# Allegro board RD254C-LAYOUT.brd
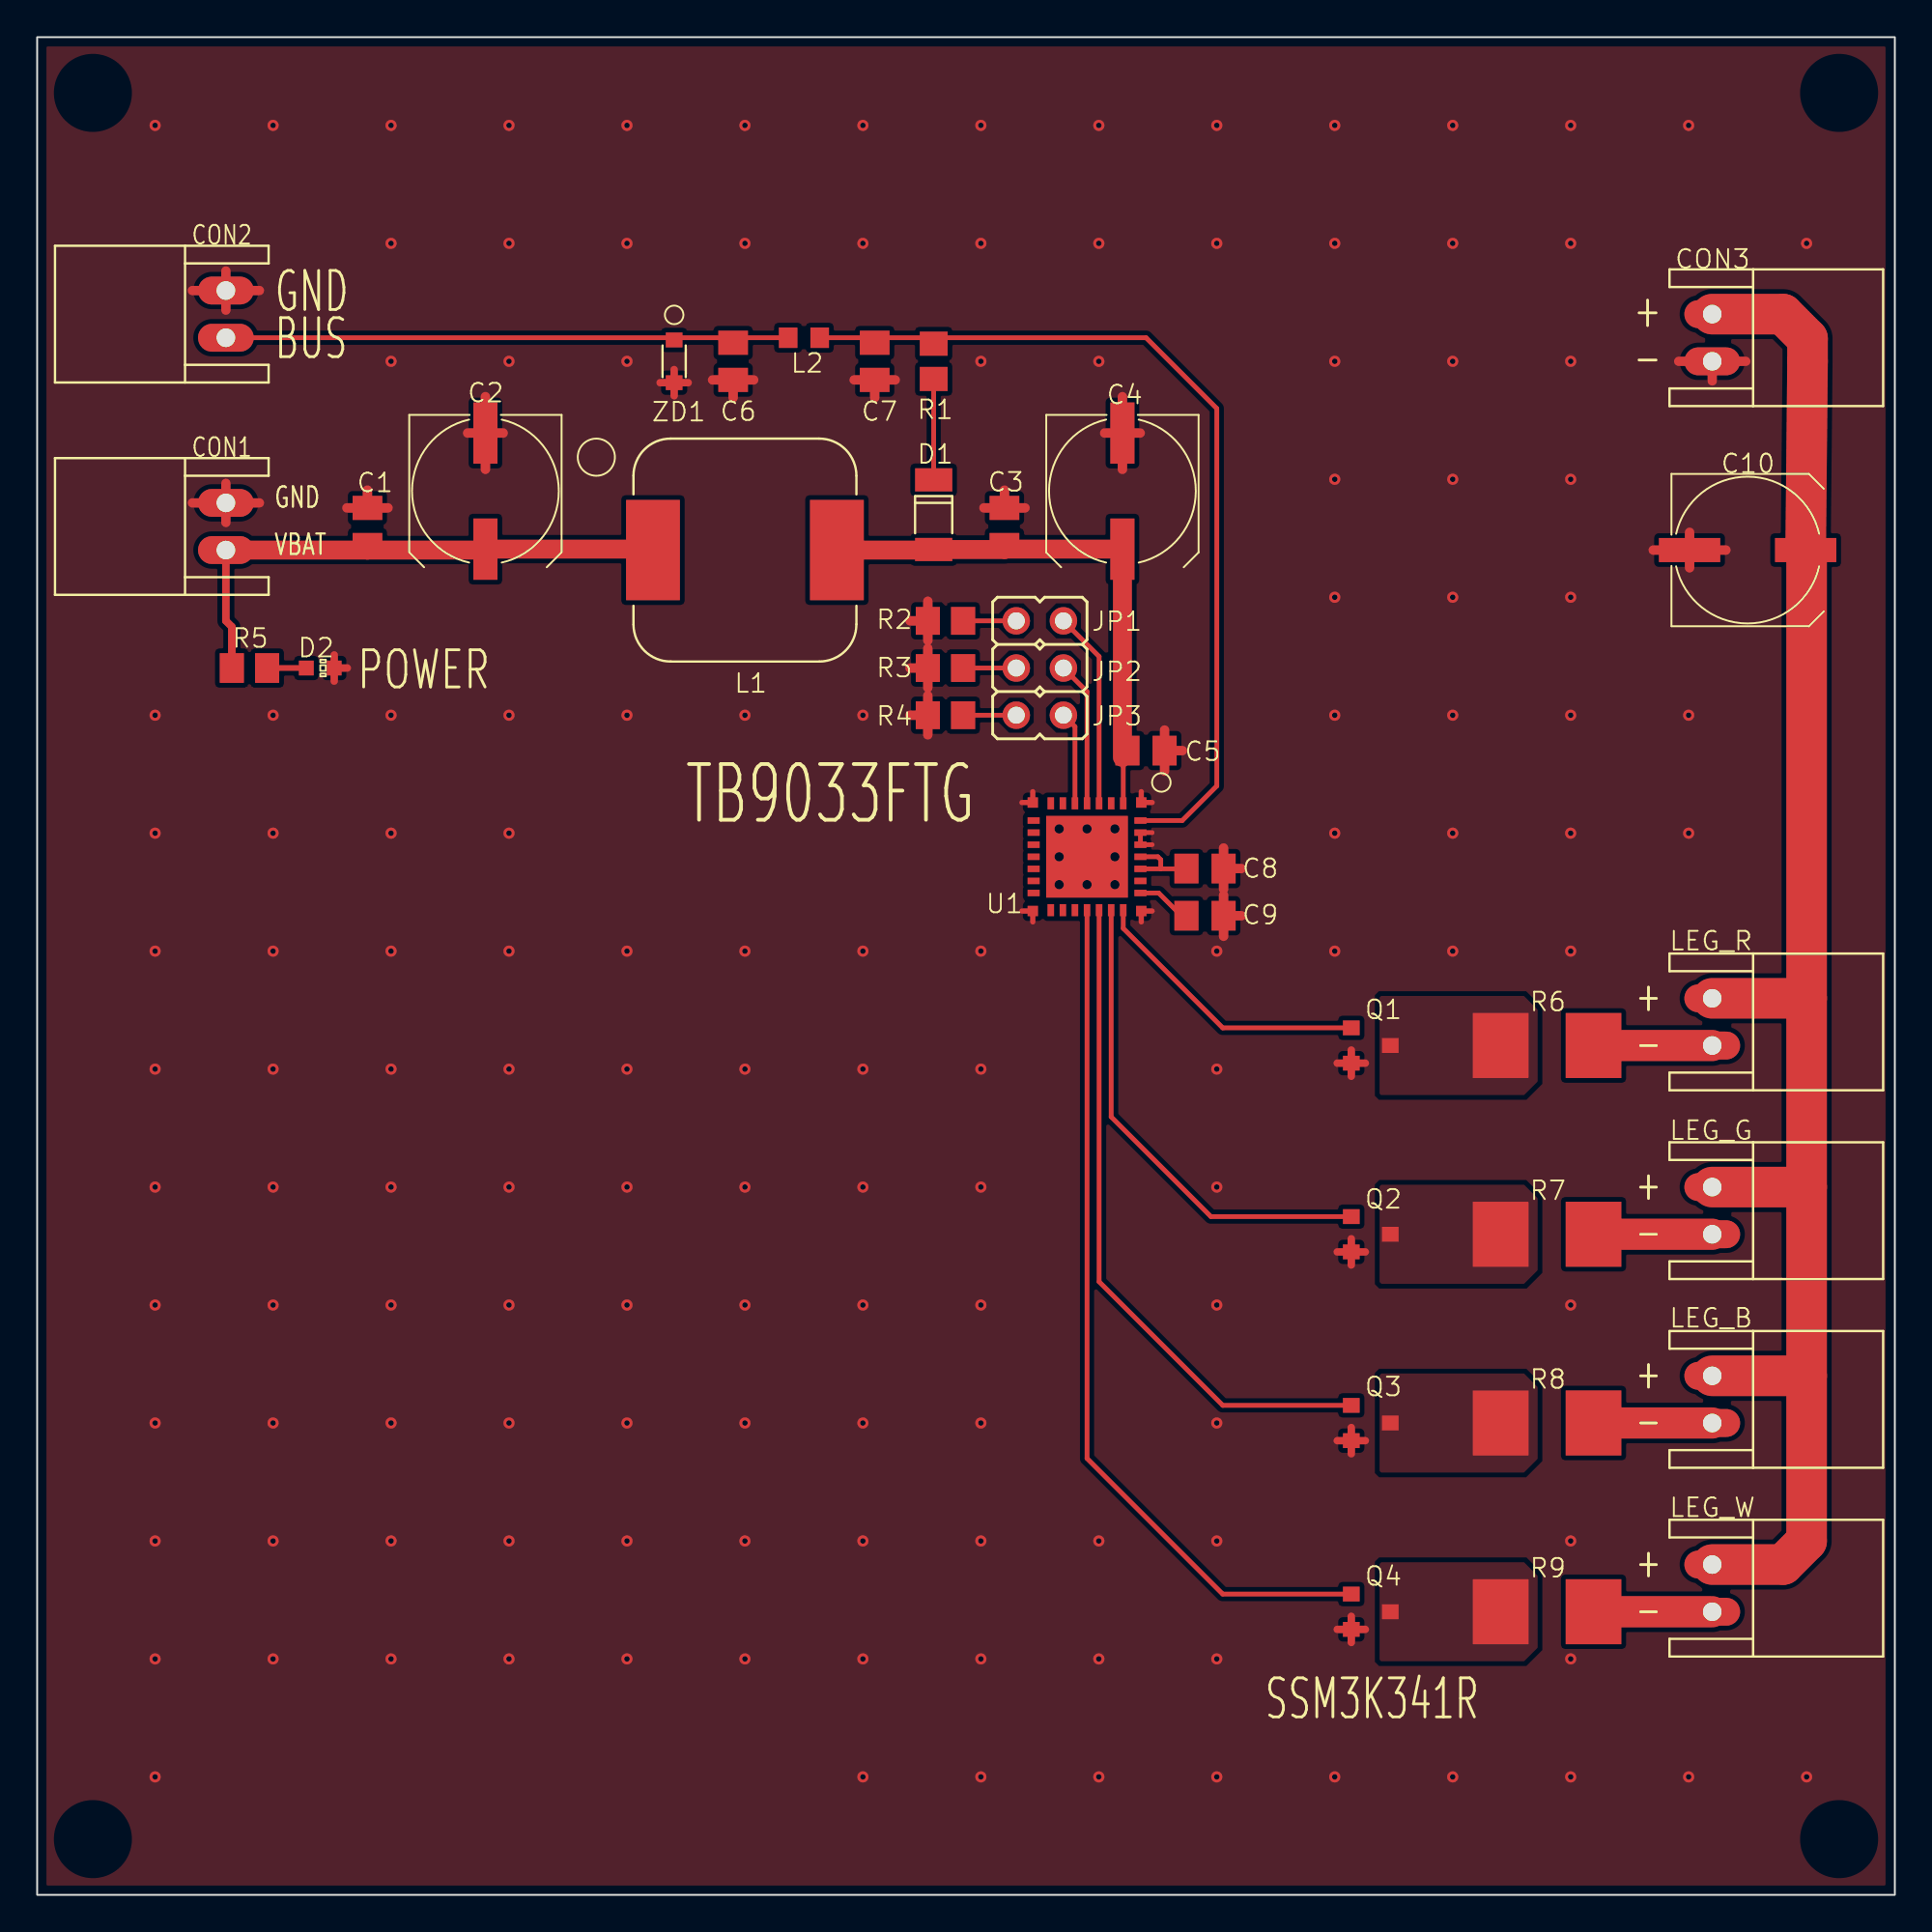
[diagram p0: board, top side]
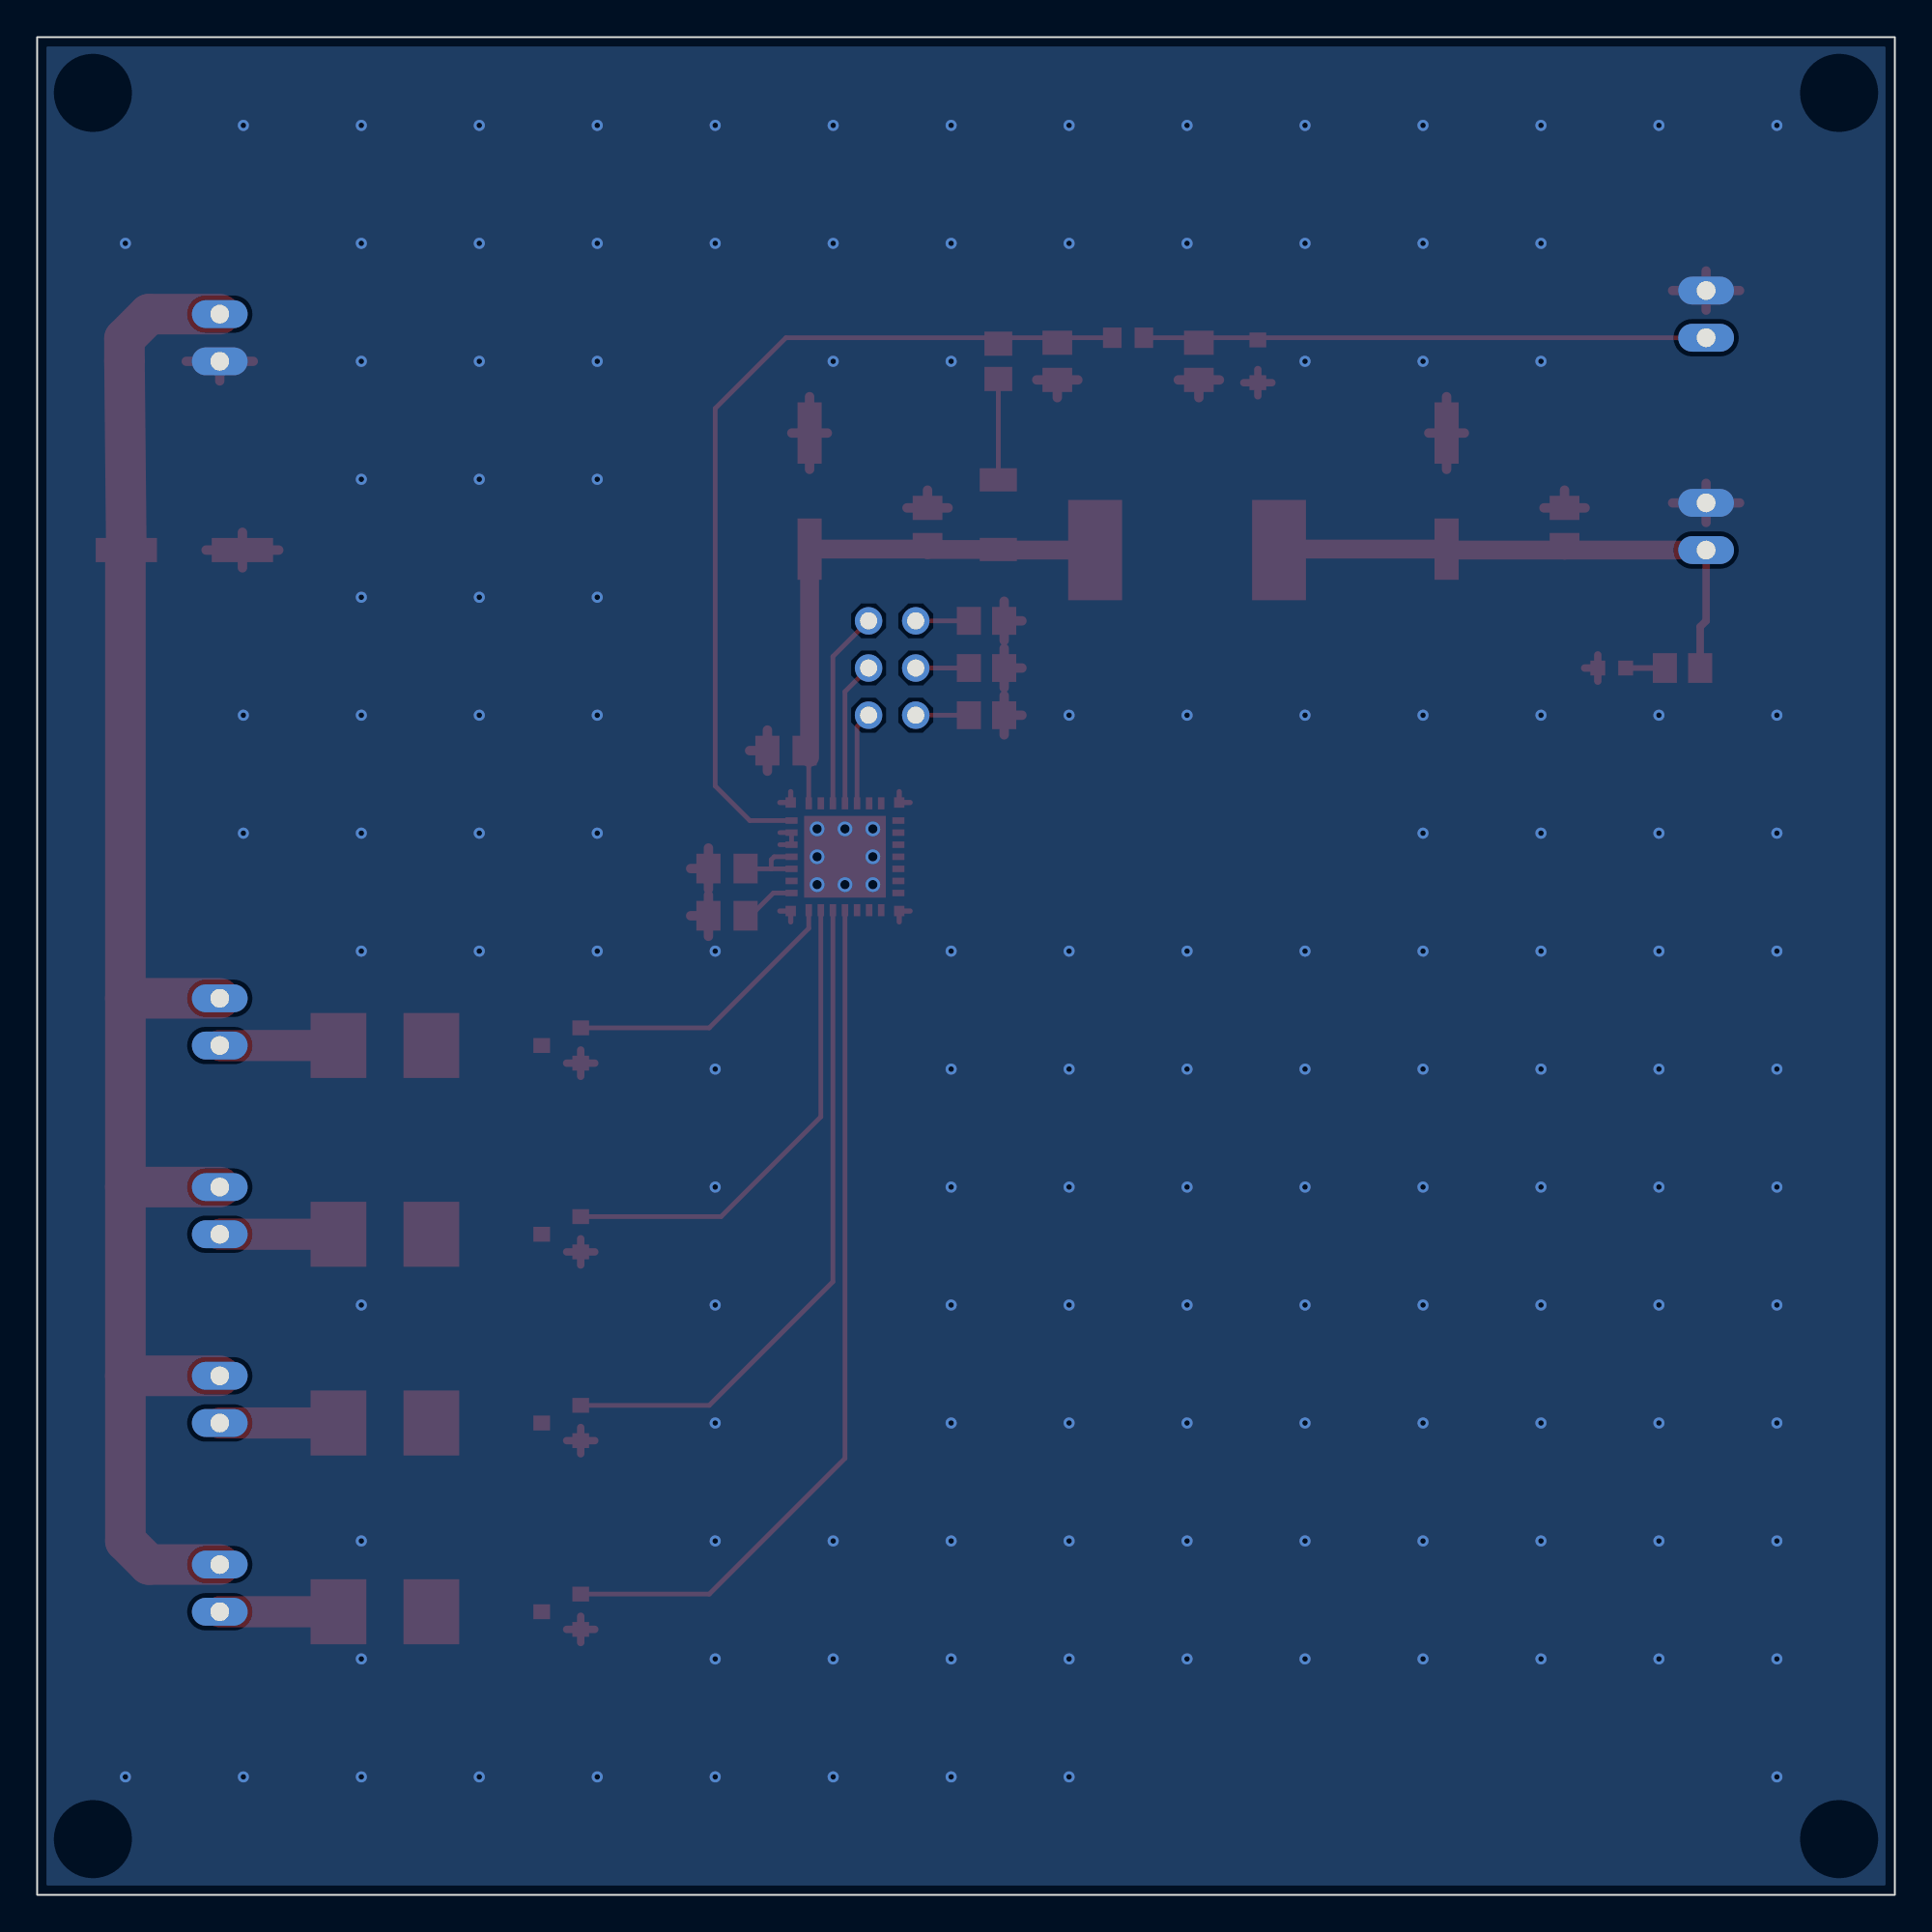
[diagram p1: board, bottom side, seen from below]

Outline 100 x 100 mm; copper layers: TOP, BOTTOM. Coordinates in mm from the lower left corner of the outline.
Outline path: rectangle 0,0 100,100

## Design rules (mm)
constraint set DEFAULT: 

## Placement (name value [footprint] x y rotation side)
C1  -  [C0805K]  17.78 73.66 90 top
C2  -  [UD_8X10_NICHICON_01]  24.13 75.56 270 top
C3  -  [C0805K]  52.07 73.66 90 top
C4  -  [UD_8X10_NICHICON_01]  58.42 75.56 270 top
C5  -  [C0805K]  59.69 61.59 0 top
C6  -  [C0805K]  37.47 82.55 270 top
C7  -  [C0805K]  45.09 82.55 270 top
C8  -  [C0805K]  62.87 55.24 180 top
C9  -  [C0805K]  62.87 52.7 180 top
C10  -  [UD_8X10_NICHICON_01]  92.08 72.39 0 top
CON1  -  [S2B_XH_A]  10.16 73.66 90 top
CON2  -  [S2B_XH_A]  10.16 85.09 90 top
CON3  -  [S2B_XH_A]  90.17 83.82 270 top
CON4  -  [S2B_XH_A]  90.17 46.99 270 top
CON5  -  [S2B_XH_A]  90.17 36.83 270 top
CON6  -  [S2B_XH_A]  90.17 26.67 270 top
CON7  -  [S2B_XH_A]  90.17 16.51 270 top
D1  -  [LL4148]  48.26 74.3 90 top
D2  -  [CHIP_LED0603]  15.24 66.04 270 top
JP1  -  [JP1]  53.98 68.58 270 top
JP2  -  [JP1]  53.98 66.04 270 top
JP3  -  [JP1]  53.98 63.5 270 top
L1  -  [7447709222]  38.1 72.39 270 top
L2  -  [R0603]  41.27 83.82 0 top
NOREF  -  []  -71 -47 0 top
Q1  -  [SOT_23F]  72.39 45.72 270 top
Q2  -  [SOT_23F]  72.39 35.56 270 top
Q3  -  [SOT_23F]  72.39 25.4 270 top
Q4  -  [SOT_23F]  72.39 15.24 270 top
R1  -  [R0805]  48.26 82.55 270 top
R2  -  [R0805]  48.9 68.58 180 top
R3  -  [R0805]  48.9 66.04 180 top
R4  -  [R0805]  48.9 63.5 180 top
R5  -  [M0805]  11.43 66.04 180 top
R6  -  [R2512_2010]  81.28 45.72 0 top
R7  -  [R2512_2010]  81.28 35.56 0 top
R8  -  [R2512_2010]  81.28 25.4 0 top
R9  -  [R2512_2010]  81.28 15.24 0 top
U1  -  [P_VQFN28_0606_0_65_003_01]  56.52 55.88 180 top
ZD1  -  [USC]  34.29 82.55 270 top

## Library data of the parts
C1 C3 C5-C9 = C0805K: alternate symbols: (T:C0805K,C1_C0805K,C3_C0805K,C5_C0805K,C6_C0805K,C7_C0805K,C8_C0805K,C9_C0805K;B:C0805K_bk)
C2 C4 C10 = UD-8X10_NICHICON_01: alternate symbols: (T:UD_8X10_NICHICON_01,C2_UD_8X10_NICHICON_01,C4_UD_8X10_NICHICON_01,C10_UD_8X10_NICHICON_01;B:UD_8X10_NICHICON_01_bk)
CON1-CON7 = S2B-XH-A: alternate symbols: (T:S2B_XH_A;B:S2B_XH_A_bk)
D1 = LL4148: alternate symbols: (T:LL4148;B:LL4148_bk)
D2 = CHIP-LED0603: alternate symbols: (T:CHIP_LED0603,D2_CHIP_LED0603;B:CHIP_LED0603_bk)
JP1-JP3 = JP1: alternate symbols: (T:JP1,JP1_JP1,JP2_JP1,JP3_JP1;B:JP1_bk)
L1 = 7447709222: alternate symbols: (T:7447709222;B:7447709222_bk)
L2 = R0603: alternate symbols: (T:R0603,L2_R0603;B:R0603_bk)
Q1-Q4 = SOT-23F: alternate symbols: (T:SOT_23F;B:SOT_23F_bk)
R1-R4 = R0805: alternate symbols: (T:R0805,R1_R0805,R2_R0805,R3_R0805,R4_R0805;B:R0805_bk)
R5 = M0805: alternate symbols: (T:M0805,R5_M0805;B:M0805_bk)
R6-R9 = R2512-2010: alternate symbols: (T:R2512_2010,R6_R2512_2010,R7_R2512_2010,R8_R2512_2010,R9_R2512_2010;B:R2512_2010_bk)
U1 = P-VQFN28-0606-0_65-003_01: alternate symbols: (T:P_VQFN28_0606_0_65_003_01,U1_P_VQFN28_0606_0_65_003_01;B:P_VQFN28_0606_0_65_003_01_bk)
ZD1 = USC: alternate symbols: (T:USC,ZD1_USC;B:USC_bk)

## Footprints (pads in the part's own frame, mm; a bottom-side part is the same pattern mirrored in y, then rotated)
7447709222
  rect 5.4x2.9 smd: 1(0,-4.95) 2(0,4.95)
C0805K
  rect 1.3x1.6 smd: 1(-1,0) 2(1,0)
CHIP_LED0603
  rect 0.8x0.8 smd: A(0,-0.75) C(0,0.75)
JP1
  round 1.48 hole 0.914: 1(0,-1.27) 2(0,1.27)
LL4148
  rect 1.25x2 smd: A(-1.875,0) K(1.875,0)
M0805
  rect 1.3x1.6 smd: 1(-0.95,0) 2(0.95,0)
P_VQFN28_0606_0_65_003_01
  rect 0.35x0.65 smd: 1(-1.95,-2.875) 2(-1.3,-2.875) 3(-0.65,-2.875) 4(0,-2.875) 5(0.65,-2.875) 6(1.3,-2.875) 7(1.95,-2.875) 15(1.95,2.875) 16(1.3,2.875) 17(0.65,2.875) 18(0,2.875) 19(-0.65,2.875) 20(-1.3,2.875) 21(-1.95,2.875)
  rect 0.56x0.56 smd: 1T(-2.92,-2.92) 2T(2.92,-2.92) 3T(2.92,2.92) 4T(-2.92,2.92)
  rect 0.65x0.35 smd: 8(2.875,-1.95) 9(2.875,-1.3) 10(2.875,-0.65) 11(2.875,0) 12(2.875,0.65) 13(2.875,1.3) 14(2.875,1.95) 22(-2.875,1.95) 23(-2.875,1.3) 24(-2.875,0.65) 25(-2.875,0) 26(-2.875,-0.65) 27(-2.875,-1.3) 28(-2.875,-1.95)
  rect 4.4x4.4 smd: E_PAD(0,0)
R0603
  rect 1x1.1 smd: 1(-0.85,0) 2(0.85,0)
R0805
  rect 1.3x1.5 smd: 1(-0.95,0) 2(0.95,0)
R2512_2010
  rect 3x3.5 smd: P_1(-2.5,0) P_2(2.5,0)
S2B_XH_A
  oval 1.5x3 hole 1: 1(1.27,0) 2(-1.27,0)
SOT_23F
  rect 0.8x0.9 smd: 1(-0.95,-1.65) 2(0.95,-1.65) 3(0,0.45)
UD_8X10_NICHICON_01
  rect 3.3x1.3 smd: 1(-3.125,0) 2(3.125,0)
USC
  rect 0.8x0.9 smd: 1(-1.15,0) 2(1.15,0)

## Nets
+12V: C1.1 C2.2 CON1.2 L1.1 R5.2
GND: C1.2 C2.1 C3.2 C4.1 C5.2 C6.2 C7.2 C8.1 C9.1 C10.1 CON1.1 CON2.1 CON3.1 D2.C Q1.2 Q2.2 Q3.2 Q4.2 R2.2 R3.2 R4.2 U1.1T U1.2T U1.3T U1.4T U1.26 U1.27 U1.E_PAD ZD1.2
VCC: C8.2 U1.24 U1.25
VDD: C9.2 U1.22
BUS: C3.1 C4.2 C5.1 C6.1 C7.1 CON2.2 D1.A D1.K L1.2 L2.1 L2.2 R1.1 R1.2 U1.1 U1.28 ZD1.1
N_2: JP1.1 JP1.2 R2.1 U1.3
N_3: JP2.1 JP2.2 R3.1 U1.4
N_4: JP3.1 JP3.2 R4.1 U1.5
N_5: C10.2 CON3.2 CON4.1 CON4.2 CON5.1 CON5.2 CON6.1 CON6.2 CON7.1 CON7.2 R6.P_2 R7.P_2 R8.P_2 R9.P_2
N_10: Q1.3 R6.P_1
N_11: Q2.3 R7.P_1
N_12: Q3.3 R8.P_1
N_13: Q4.3 R9.P_1
N_14: Q1.1 U1.21
N_15: Q2.1 U1.20
N_16: Q3.1 U1.19
N_17: Q4.1 U1.18
N_30: D2.A R5.1

Pads without a net: U1 2 6 7 8 9 10 11 12 13 14 15 16 17 23

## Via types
v1: diameter 0.6, hole 0.3, TOP to BOTTOM, 140 vias
v2: diameter 0.8, hole 0.5, TOP to BOTTOM, 8 vias

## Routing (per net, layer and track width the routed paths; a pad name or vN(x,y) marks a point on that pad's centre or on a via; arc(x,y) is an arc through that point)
+12V: length 29.8
  TOP w0.406: R5.2 10.48,68.26 10.16,68.58 CON1.2
  TOP w1.016: L1.1 33.15,72.44 C2.2 24.13,72.39 17.78,72.39 ; 17.78,72.39 C1.1 ; 17.78,72.39 CON1.2
GND: length 88.2
  TOP w0.254: 60.02,56.53 U1.26 U1.27 60.02,57.18
  TOP w0.28: 59.44,52.38 U1.4T 60.02,52.96 ; 53.01,58.8 U1.2T 53.59,59.38 ; 53.01,52.96 U1.3T 53.59,52.38 ; 60.02,58.8 U1.1T 59.44,59.38
  TOP w0.4: ZD1.2 34.29,82.11 ; ZD1.2 34.29,80.69 ; ZD1.2 33.53,81.4 ; ZD1.2 35.05,81.4 ; D2.C 15.99,66.75 ; D2.C 16.7,66.04 ; D2.C 15.99,65.33 ; 70.74,13.59 Q4.2 ; Q4.2 69.98,14.29 ; Q4.2 70.74,14.99 ; Q4.2 71.5,14.29 ; Q2.2 70.74,35.31 ; Q2.2 69.98,34.61 ; Q2.2 70.74,33.91 ; Q2.2 71.5,34.61 ; Q1.2 71.5,44.77 ; Q1.2 69.98,44.77 ; Q1.2 70.74,44.06 ; Q1.2 70.74,45.48 ; Q3.2 70.74,25.16 ; Q3.2 69.98,24.45 ; Q3.2 70.74,23.75 ; Q3.2 71.5,24.45
  TOP w0.5: CON3.1 91.97,82.55 ; CON3.1 88.36,82.55 ; CON3.1 90.17,81.5 ; 8.36,74.93 CON1.1 ; CON1.1 10.16,73.88 ; CON1.1 11.96,74.93 ; CON1.1 10.16,75.98 ; 10.16,85.31 CON2.1 ; CON2.1 11.96,86.36 ; CON2.1 10.16,87.42 ; CON2.1 8.36,86.36
  TOP w0.508: 46.99,68.58 R2.2 ; R2.2 47.95,69.64 ; R2.2 47.95,67.53 ; 46.99,66.04 R3.2 ; R3.2 47.95,67.09 ; R3.2 47.95,64.98 ; 57.47,78.69 C4.1 ; C4.1 58.42,76.73 ; C4.1 58.42,80.64 ; C4.1 59.38,78.69 ; C5.2 60.69,62.7 ; C5.2 60.69,60.49 ; C5.2 61.65,61.59 ; C9.1 64.82,52.7 ; C9.1 63.87,53.81 ; C9.1 63.87,51.6 ; C7.2 46.19,81.55 ; C7.2 43.98,81.55 ; C7.2 45.09,80.59 ; 63.87,54.14 C8.1 ; C8.1 63.87,56.35 ; C8.1 64.82,55.24 ; C1.2 18.89,74.66 ; C1.2 16.68,74.66 ; C1.2 17.78,75.61 ; 24.13,76.73 C2.1 ; C2.1 25.09,78.69 ; C2.1 24.13,80.64 ; C2.1 23.18,78.69 ; C3.2 53.17,74.66 ; C3.2 52.07,75.61 ; C3.2 50.97,74.66 ; C6.2 38.57,81.55 ; C6.2 37.47,80.59 ; C6.2 36.36,81.55 ; 87,72.39 C10.1 ; C10.1 90.91,72.39 ; C10.1 88.95,73.34 ; C10.1 88.95,71.44 ; R4.2 47.95,64.56 ; R4.2 46.99,63.5 ; R4.2 47.95,62.45
  vias: v1(6.35,95.25) v1(6.35,63.5) v1(6.35,57.15) v1(6.35,50.8) v1(6.35,44.45) v1(6.35,38.1) v1(6.35,31.75) v1(6.35,25.4) v1(6.35,19.05) v1(6.35,12.7) v1(6.35,6.35) v1(12.7,95.25) v1(12.7,63.5) v1(12.7,57.15) v1(12.7,50.8) v1(12.7,44.45) v1(12.7,38.1) v1(12.7,31.75) v1(12.7,25.4) v1(12.7,19.05) v1(12.7,12.7) v1(19.05,95.25) v1(19.05,88.9) v1(19.05,82.55) v1(19.05,63.5) v1(19.05,57.15) v1(19.05,50.8) v1(19.05,44.45) v1(19.05,38.1) v1(19.05,31.75) v1(19.05,25.4) v1(19.05,19.05) v1(19.05,12.7) v1(25.4,95.25) v1(25.4,88.9) v1(25.4,82.55) v1(25.4,63.5) v1(25.4,57.15) v1(25.4,50.8) v1(25.4,44.45) v1(25.4,38.1) v1(25.4,31.75) v1(25.4,25.4) v1(25.4,19.05) v1(25.4,12.7) v1(31.75,95.25) v1(31.75,88.9) v1(31.75,82.55) v1(31.75,63.5) v1(31.75,50.8) v1(31.75,44.45) v1(31.75,38.1) v1(31.75,31.75) v1(31.75,25.4) v1(31.75,19.05) v1(31.75,12.7) v1(38.1,95.25) v1(38.1,88.9) v1(38.1,63.5) v1(38.1,50.8) v1(38.1,44.45) v1(38.1,38.1) v1(38.1,31.75) v1(38.1,25.4) v1(38.1,19.05) v1(38.1,12.7) v1(44.45,95.25) v1(44.45,88.9) v1(44.45,63.5) v1(44.45,50.8) v1(44.45,44.45) v1(44.45,38.1) v1(44.45,31.75) v1(44.45,25.4) v1(44.45,19.05) v1(44.45,12.7) v1(44.45,6.35) v1(50.8,95.25) v1(50.8,88.9) v1(50.8,82.55) v1(50.8,50.8) v1(50.8,44.45) v1(50.8,38.1) v1(50.8,31.75) v1(50.8,25.4) v1(50.8,19.05) v1(50.8,12.7) v1(50.8,6.35) v1(57.15,95.25) v1(57.15,88.9) v1(57.15,82.55) v1(57.15,19.05) v1(57.15,12.7) v1(57.15,6.35) v1(63.5,95.25) v1(63.5,88.9) v1(63.5,50.8) v1(63.5,44.45) v1(63.5,38.1) v1(63.5,31.75) v1(63.5,25.4) v1(63.5,19.05) v1(63.5,12.7) v1(63.5,6.35) v1(69.85,95.25) v1(69.85,88.9) v1(69.85,82.55) v1(69.85,76.2) v1(69.85,69.85) v1(69.85,63.5) v1(69.85,57.15) v1(69.85,50.8) v1(69.85,6.35) v1(76.2,95.25) v1(76.2,88.9) v1(76.2,82.55) v1(76.2,76.2) v1(76.2,69.85) v1(76.2,63.5) v1(76.2,57.15) v1(76.2,50.8) v1(76.2,6.35) v1(82.55,95.25) v1(82.55,88.9) v1(82.55,82.55) v1(82.55,76.2) v1(82.55,69.85) v1(82.55,63.5) v1(82.55,57.15) v1(82.55,50.8) v1(82.55,31.75) v1(82.55,19.05) v1(82.55,12.7) v1(82.55,6.35) v1(88.9,95.25) v1(88.9,63.5) v1(88.9,57.15) v1(88.9,6.35) v1(95.25,88.9) v1(95.25,6.35) v2(55.02,57.38) v2(55.02,55.88) v2(55.02,54.38) v2(56.52,57.38) v2(56.52,54.38) v2(58.02,57.38) v2(58.02,55.88) v2(58.02,54.38)
VCC: length 4.1
  TOP w0.254: U1.25 60.33,55.88 60.48,55.72 60.48,55.23 ; U1.24 60.48,55.23 ; 60.48,55.23 61.85,55.23 C8.2
VDD: length 3
  TOP w0.254: U1.22 60.37,53.93 61.59,52.7 C9.2
BUS: length 115.1
  TOP w0.254: D1.K R1.2 ; L2.1 37.73,83.82 C6.1 37.2,83.82 34.29,83.82 ZD1.1 34.17,83.82 CON2.2 ; 58.42,61.23 C5.1 58.47,60.73 U1.1 ; L2.2 44.81,83.82 C7.1 45.45,83.55 45.72,83.82 47.94,83.82 R1.1 48.26,83.82 59.69,83.82 63.5,80.01 63.5,59.69 61.64,57.83 U1.28
  TOP w1.016: 52.07,72.44 C4.2 58.42,61.23 ; 52.07,72.44 52.07,72.42 D1.A 48.26,72.39 L1.2 ; 52.07,72.44 C3.1
N_2: length 13.8
  TOP w0.254: U1.3 57.16,66.66 55.24,68.58 ; 49.53,68.58 JP1.1
N_3: length 10.7
  TOP w0.254: JP2.1 49.84,66.04 ; U1.4 56.52,64.77 55.24,66.04
N_4: length 7.9
  TOP w0.254: U1.5 55.87,62.88 55.24,63.5 ; JP3.1 49.84,63.5
N_5: length 116.9
  TOP w0.406: C10.2 95.25,72.34 95.25,71.75
  TOP w1.676: R8.P_2 CON6.1 ; R7.P_2 CON5.1 ; R9.P_2 CON7.1 ; CON4.1 R6.P_2
  TOP w2.184: 95.25,27.94 95.25,19.05 93.98,17.78 CON7.2 ; 95.25,27.94 CON6.2 ; 95.25,27.94 95.25,38.1 ; 95.25,72.39 95.2,72.34 C10.2 95.3,82.55 95.3,83.77 93.98,85.09 CON3.2 ; 95.25,71.75 95.25,48.26 ; 95.25,48.26 CON4.2 ; 95.25,48.26 95.25,38.1 ; 95.25,38.1 CON5.2
N_14: length 15.5
  TOP w0.254: U1.21 58.47,52.02 63.82,46.67 Q1.1
N_15: length 26.3
  TOP w0.254: U1.20 57.81,41.88 63.19,36.51 Q2.1
N_16: length 36.3
  TOP w0.254: Q3.1 63.82,26.35 57.16,33.01 U1.19
N_17: length 46.8
  TOP w0.254: Q4.1 63.82,16.19 56.52,23.5 U1.18
N_30: length 2.1
  TOP w0.305: R5.1 D2.A

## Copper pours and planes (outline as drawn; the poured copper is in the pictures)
GND on TOP: 99.5,0.57 99.48,0.52 99.43,0.5 0.57,0.5 0.52,0.52 0.5,0.57 0.5,99.43 0.52,99.48 0.57,99.5 99.43,99.5 99.48,99.48 99.5,99.43 ; 24 cut-outs
GND on BOTTOM: 99.5,0.57 99.48,0.52 99.43,0.5 0.57,0.5 0.52,0.52 0.5,0.57 0.5,99.43 0.52,99.48 0.57,99.5 99.43,99.5 99.48,99.48 99.5,99.43 ; 21 cut-outs
N_10 on TOP: 72.37,43.05 72.34,43.06 72.32,43.08 72.28,43.11 72.27,43.13 72.26,43.16 72.26,48.28 72.27,48.3 72.28,48.33 72.32,48.37 72.35,48.38 72.37,48.39 80.01,48.39 80.03,48.38 80.06,48.37 80.75,47.67 80.77,47.65 80.77,47.62 80.77,43.81 80.77,43.78 80.75,43.76 80.07,43.08 80.04,43.06 80.01,43.05
N_11 on TOP: 72.39,32.89 72.36,32.9 72.34,32.91 72.28,32.97 72.27,32.99 72.26,33.02 72.26,38.11 72.27,38.13 72.28,38.16 72.33,38.2 72.36,38.22 72.38,38.23 80.01,38.23 80.04,38.22 80.07,38.2 80.75,37.52 80.77,37.5 80.77,37.47 80.77,33.66 80.77,33.63 80.75,33.6 80.06,32.91 80.04,32.9 80.01,32.89
N_12 on TOP: 72.38,22.73 72.35,22.74 72.32,22.75 72.28,22.79 72.27,22.82 72.26,22.85 72.26,27.94 72.27,27.97 72.28,27.99 72.34,28.05 72.36,28.06 72.39,28.07 80.01,28.07 80.04,28.06 80.06,28.05 80.75,27.36 80.77,27.33 80.77,27.3 80.77,23.5 80.77,23.47 80.75,23.45 80.06,22.75 80.03,22.74 80.01,22.73
N_13 on TOP: 72.38,12.57 72.35,12.58 72.32,12.6 72.28,12.63 72.27,12.66 72.26,12.69 72.26,17.78 72.27,17.81 72.28,17.84 72.33,17.89 72.36,17.9 72.39,17.91 80.01,17.91 80.04,17.9 80.06,17.89 80.75,17.2 80.77,17.17 80.77,17.14 80.77,13.33 80.77,13.31 80.75,13.28 80.06,12.6 80.04,12.58 80.01,12.57

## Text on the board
Ref Des/Silkscreen Top: CON2 | CON1 | GND | VBAT | R5 | D2 | C1 | C2 | ZD1 | C6 | L1 | L2 | C7 | R2 | R3 | R4 | R1 | D1 | U1 | C3 | JP1 | JP2 | JP3 | C4 | C5 | C8 | C9 | Q1 | Q2 | Q3 | Q4 | R6 | R7 | R8 | R9 | LEG_R | LEG_G | LEG_B | LEG_W | CON3 | C10 | + | - | BUS | SSM3K341R | POWER | TB9033FTG
SYMBOL-1-TOP: VALUE
SYMBOL-2-TOP: VALUE
